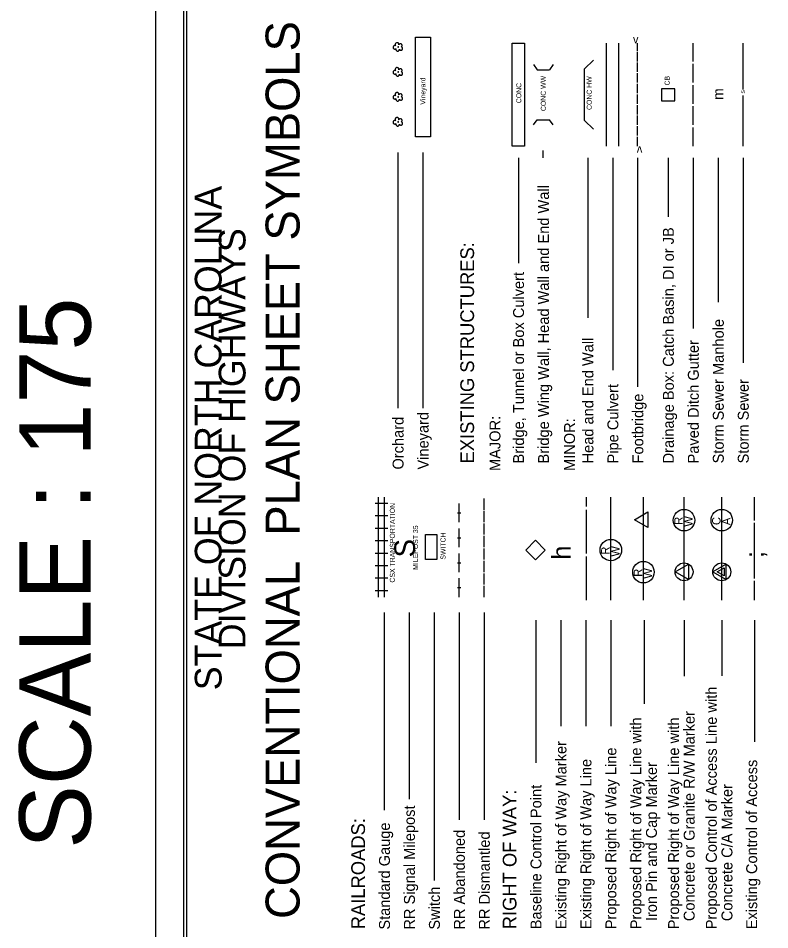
# Model space of a CAD drawing. Extents: x 2026893 to 2039781, y 729195 to 739590.
# Drawn here: x 2035191 to 2037298, y 735661 to 738217 of the extents above; entities that cross this region are included whole.
import ezdxf

# ---------------------------------------------------------------- set-up
doc = ezdxf.new("R2010")
doc.units = 0
for name, color, linetype in [('Scratch_Level_3', 7, 'Continuous'), ('Sheet Cutting Line CELL', 7, 'Continuous'), ('Sheet Plot Border Inside CELL', 7, 'Continuous'), ('Sheet Plot Border Outside CELL', 7, 'Continuous'), ('Sheet Symbology CELL', 7, 'Continuous')]:
    doc.layers.add(name, color=color, linetype=linetype)

msp = doc.modelspace()

# ---------------------------------------------------------------- linework, layer by layer
at = {"layer": 'Scratch_Level_3'}
msp.add_lwpolyline([(2036640.9, 736698.3), (2036613.5, 736725.7), (2036640.9, 736753.1), (2036668.3, 736725.7)], close=True, dxfattribs=at)
at = {"layer": 'Sheet Cutting Line CELL'}
msp.add_line((2035575.3, 739589.9), (2035575.3, 733695.9), dxfattribs=at)
at = {"layer": 'Sheet Plot Border Inside CELL'}
msp.add_lwpolyline([(2039346.7, 733741.4), (2039346.7, 739574.2), (2035653.9, 739574.2), (2035653.9, 733741.4)], close=True, dxfattribs=at)
at = {"layer": 'Sheet Plot Border Outside CELL'}
msp.add_lwpolyline([(2039425.3, 733695.9), (2039425.3, 739589.9), (2035575.3, 739589.9), (2035575.3, 733695.9)], close=True, dxfattribs=at)
at = {"layer": 'Sheet Symbology CELL'}
for p, q in [((2036839.7, 737858.5), (2036839.7, 738147.3)), ((2036874.7, 737858.5), (2036874.7, 738147.3)), ((2036927.2, 738126.3), (2036927.2, 738147.3)), ((2037082.7, 738096.5), (2037082.7, 738147.3)), ((2037222.7, 738017.9), (2037222.7, 738147.3)), ((2036927.2, 738096.5), (2036927.2, 738122.8)), ((2036635.2, 738087.3), (2036645.2, 738072.9)), ((2036690.2, 738087.3), (2036680.2, 738072.9)), ((2036778.5, 738075.1), (2036803.2, 738099.9)), ((2036927.2, 738066.8), (2036927.2, 738093)), ((2037082.7, 738037), (2037082.7, 738089.5)), ((2036645.2, 738072.9), (2036680.2, 738072.9)), ((2036778.5, 737930.7), (2036778.5, 738075.1)), ((2036927.2, 738037), (2036927.2, 738063.3)), ((2036927.2, 738007.3), (2036927.2, 738033.5)), ((2037082.7, 737977.5), (2037082.7, 738030)), ((2036927.2, 737977.5), (2036927.2, 738003.8)), ((2037222.7, 737858.5), (2037222.7, 738000.4)), ((2036927.2, 737947.8), (2036927.2, 737974)), ((2037082.7, 737918), (2037082.7, 737970.5)), ((2036635.2, 737918.6), (2036645.2, 737932.9)), ((2036645.2, 737932.9), (2036680.2, 737932.9)), ((2036690.2, 737918.6), (2036680.2, 737932.9)), ((2036803.2, 737906), (2036778.5, 737930.7)), ((2036927.2, 737918), (2036927.2, 737944.3)), ((2036927.2, 737888.3), (2036927.2, 737914.5)), ((2037082.7, 737858.5), (2037082.7, 737911)), ((2036927.2, 737858.5), (2036927.2, 737884.8)), ((2036255.1, 737841.1), (2036255.1, 737123.8)), ((2036325.1, 737841.1), (2036325.1, 737123.8)), ((2036592.7, 737826), (2036592.7, 737530.5)), ((2036662.7, 737826), (2036662.7, 737846.9)), ((2036787.2, 737826), (2036787.2, 737376.9)), ((2036857.2, 737826), (2036857.2, 737230.3)), ((2036927.2, 737826), (2036927.2, 737183.8)), ((2037012.7, 737826), (2037012.7, 737660.8)), ((2037082.7, 737826), (2037082.7, 737346.7)), ((2037152.7, 737826), (2037152.7, 737421.1)), ((2037222.7, 737826), (2037222.7, 737251.3)), ((2036226.4, 736856.4), (2036191.4, 736856.4)), ((2036200.2, 736838.9), (2036200.2, 736873.9)), ((2036217.7, 736838.9), (2036217.7, 736873.9)), ((2036426.8, 736803.9), (2036426.8, 736856.4)), ((2036496.8, 736838.9), (2036496.8, 736870.4)), ((2036783.6, 736847.7), (2036783.6, 736873.9)), ((2036852, 736585.2), (2036852, 736873.9)), ((2036943.4, 736585.2), (2036943.4, 736873.9)), ((2037057.2, 736585.2), (2037057.2, 736873.9)), ((2037163, 736585.2), (2037163, 736873.9)), ((2037254.3, 736808.7), (2037254.3, 736873.9)), ((2036200.2, 736803.9), (2036200.2, 736838.9)), ((2036217.7, 736803.9), (2036217.7, 736838.9)), ((2036422.5, 736830.2), (2036431.2, 736830.2)), ((2036496.8, 736803.9), (2036496.8, 736835.4)), ((2036783.6, 736716.4), (2036783.6, 736838.9)), ((2036226.4, 736821.4), (2036191.4, 736821.4)), ((2036200.2, 736768.9), (2036200.2, 736803.9)), ((2036217.7, 736768.9), (2036217.7, 736803.9)), ((2036943.4, 736810.8), (2036943.4, 736810.8)), ((2037254.3, 736646.3), (2037254.3, 736801.7)), ((2036226.4, 736786.4), (2036191.4, 736786.4)), ((2036426.8, 736733.9), (2036426.8, 736786.4)), ((2036496.8, 736768.9), (2036496.8, 736800.4)), ((2036226.4, 736751.4), (2036191.4, 736751.4)), ((2036200.2, 736733.9), (2036200.2, 736768.9)), ((2036217.7, 736733.9), (2036217.7, 736768.9)), ((2036422.5, 736760.2), (2036431.2, 736760.2)), ((2036496.8, 736733.9), (2036496.8, 736765.4)), ((2036200.2, 736698.9), (2036200.2, 736733.9)), ((2036217.7, 736698.9), (2036217.7, 736733.9)), ((2036496.8, 736698.9), (2036496.8, 736730.4)), ((2036226.4, 736716.4), (2036191.4, 736716.4)), ((2036426.8, 736663.9), (2036426.8, 736716.4)), ((2036783.6, 736585.2), (2036783.6, 736707.7)), ((2036226.4, 736681.4), (2036191.4, 736681.4)), ((2036200.2, 736663.9), (2036200.2, 736698.9)), ((2036217.7, 736663.9), (2036217.7, 736698.9)), ((2036422.5, 736690.2), (2036431.2, 736690.2)), ((2036496.8, 736663.9), (2036496.8, 736695.4)), ((2036200.2, 736628.9), (2036200.2, 736663.9)), ((2036217.7, 736628.9), (2036217.7, 736663.9)), ((2036496.8, 736628.9), (2036496.8, 736660.4)), ((2037057.2, 736664.6), (2037057.2, 736664.6)), ((2037163, 736664.6), (2037163, 736664.6)), ((2036226.4, 736646.4), (2036191.4, 736646.4)), ((2036200.2, 736593.9), (2036200.2, 736628.9)), ((2036217.7, 736593.9), (2036217.7, 736628.9)), ((2036426.8, 736593.9), (2036426.8, 736646.4)), ((2036496.8, 736593.9), (2036496.8, 736625.4)), ((2037254.3, 736585.2), (2037254.3, 736639.3)), ((2036226.4, 736611.4), (2036191.4, 736611.4)), ((2036422.5, 736620.2), (2036431.2, 736620.2)), ((2036216.8, 736550.6), (2036216.8, 735996.1)), ((2036286.8, 736550.6), (2036286.8, 736027.1)), ((2036356.8, 736550.6), (2036356.8, 735798.4)), ((2036426.8, 736550.6), (2036426.8, 735969)), ((2036496.8, 736550.6), (2036496.8, 735969)), ((2036496.8, 736550.6), (2036496.8, 735969)), ((2036641.6, 736529.1), (2036641.6, 736129.3)), ((2036711.6, 736529.1), (2036711.6, 736231.8)), ((2036781.6, 736529.1), (2036781.6, 736231.8)), ((2036851.6, 736529.1), (2036851.6, 736231.8)), ((2036945.5, 736529.1), (2036945.5, 736294.2)), ((2037057.7, 736529.1), (2037057.7, 736371.6)), ((2037163.5, 736529.1), (2037163.5, 736372.9)), ((2037254.3, 736529.1), (2037254.3, 736187.7))]:
    msp.add_line(p, q, dxfattribs=at)
for points in [[(2035662.8, 739530.4), (2035662.8, 734280.4), (2039334.3, 734280.4), (2039334.3, 739530.4)], [(2037031.3, 737986.1), (2037031.3, 738019.7), (2036994.1, 738019.7), (2036994.1, 737986.1)], [(2036956, 736788.9), (2036918.2, 736810.8), (2036956, 736832.6)], [(2036332.5, 736698.9), (2036332.5, 736768.9), (2036364.3, 736768.9), (2036364.3, 736698.9)], [(2037069.8, 736642.8), (2037032, 736664.6), (2037069.8, 736686.5)], [(2037175.6, 736642.8), (2037175.6, 736686.5), (2037137.8, 736664.6)], [(2037169.6, 736653.2), (2037149.9, 736664.6), (2037169.6, 736676.1)]]:
    msp.add_lwpolyline(points, close=True, dxfattribs=at)
for points in [[(2036304.1, 737884.5), (2036304.1, 738164.5), (2036346.1, 738164.5), (2036346.1, 737884.5), (2036304.1, 737884.5)], [(2036249, 738140.1), (2036247.9, 738140.7), (2036246.9, 738140.8), (2036245.8, 738140.7), (2036244.8, 738140.5), (2036243.9, 738140), (2036243, 738139.4), (2036242.3, 738138.6), (2036241.8, 738137.7), (2036241.4, 738136.5), (2036241.4, 738135.6), (2036241.6, 738134.5), (2036242, 738133.5), (2036242.5, 738132.6), (2036243.2, 738131.7), (2036244.2, 738131.2), (2036245.1, 738130.9), (2036246.2, 738130.7), (2036247.2, 738130.7), (2036248.3, 738130.9), (2036249.1, 738131.4), (2036250.2, 738132.1), (2036249.7, 738131.2), (2036249.5, 738130.2), (2036249.5, 738129.1), (2036249.8, 738128.2), (2036250.2, 738127.4), (2036250.9, 738126.5), (2036251.6, 738125.8), (2036252.5, 738125.3), (2036253.3, 738125.1), (2036254.6, 738124.9), (2036255.4, 738125.1), (2036256.3, 738125.4), (2036257.2, 738126.1), (2036257.9, 738126.7), (2036258.4, 738127.5), (2036258.9, 738128.6), (2036259.1, 738129.5), (2036259.1, 738130.5), (2036259.5, 738129.6), (2036260.2, 738128.8), (2036260.9, 738128.2), (2036261.9, 738127.9), (2036263, 738127.5), (2036263.8, 738127.5), (2036264.9, 738127.7), (2036265.8, 738128.2), (2036266.6, 738128.8), (2036267.3, 738129.5), (2036267.9, 738130.3), (2036268.2, 738131.2), (2036268.2, 738132.3), (2036268.2, 738133.3), (2036268, 738134.2), (2036267.3, 738135.1), (2036266.8, 738135.9), (2036265.2, 738136.8)], [(2036265.2, 738136.8), (2036266.5, 738138.9), (2036266.8, 738140), (2036267, 738141), (2036266.8, 738142.1), (2036266.5, 738142.9), (2036265.9, 738143.8), (2036265.2, 738144.7), (2036264.4, 738145.2), (2036263.5, 738145.6), (2036262.4, 738145.9), (2036261.4, 738145.7), (2036260.3, 738145.6), (2036259.3, 738144.9), (2036258.6, 738144.3), (2036258.1, 738143.5), (2036257.5, 738142.4), (2036257.7, 738143.5), (2036257.7, 738144.7), (2036257.4, 738145.6), (2036256.8, 738146.6), (2036256.3, 738147.5), (2036255.4, 738148.2), (2036254.4, 738148.7), (2036253.3, 738148.9), (2036252.3, 738149.1), (2036251.2, 738148.9), (2036250.2, 738148.5), (2036249.3, 738147.8), (2036248.4, 738147), (2036247.9, 738146.1), (2036247.6, 738145), (2036247.4, 738144), (2036247.4, 738142.9), (2036247.7, 738141.9), (2036248.3, 738141), (2036249, 738140.1)], [(2036255.1, 738137.2), (2036255.1, 738136.6), (2036255.3, 738136.3), (2036255.4, 738135.9), (2036256, 738135.9), (2036256.3, 738135.9), (2036256.7, 738136.3), (2036256.7, 738136.8), (2036256.7, 738137.2), (2036256.3, 738137.5), (2036255.8, 738137.7), (2036255.4, 738137.5), (2036255.1, 738137.2)], [(2036575.2, 737858.5), (2036575.2, 738147.3), (2036610.2, 738147.3), (2036610.2, 737858.5), (2036575.2, 737858.5)], [(2036249, 738070.1), (2036247.9, 738070.7), (2036246.9, 738070.8), (2036245.8, 738070.7), (2036244.8, 738070.5), (2036243.9, 738070), (2036243, 738069.4), (2036242.3, 738068.6), (2036241.8, 738067.7), (2036241.4, 738066.5), (2036241.4, 738065.6), (2036241.6, 738064.5), (2036242, 738063.5), (2036242.5, 738062.6), (2036243.2, 738061.7), (2036244.2, 738061.2), (2036245.1, 738060.9), (2036246.2, 738060.7), (2036247.2, 738060.7), (2036248.3, 738060.9), (2036249.1, 738061.4), (2036250.2, 738062.1), (2036249.7, 738061.2), (2036249.5, 738060.2), (2036249.5, 738059.1), (2036249.8, 738058.2), (2036250.2, 738057.4), (2036250.9, 738056.5), (2036251.6, 738055.8), (2036252.5, 738055.3), (2036253.3, 738055.1), (2036254.6, 738054.9), (2036255.4, 738055.1), (2036256.3, 738055.4), (2036257.2, 738056.1), (2036257.9, 738056.7), (2036258.4, 738057.5), (2036258.9, 738058.6), (2036259.1, 738059.5), (2036259.1, 738060.5), (2036259.5, 738059.6), (2036260.2, 738058.8), (2036260.9, 738058.2), (2036261.9, 738057.9), (2036263, 738057.5), (2036263.8, 738057.5), (2036264.9, 738057.7), (2036265.8, 738058.2), (2036266.6, 738058.8), (2036267.3, 738059.5), (2036267.9, 738060.3), (2036268.2, 738061.2), (2036268.2, 738062.3), (2036268.2, 738063.3), (2036268, 738064.2), (2036267.3, 738065.1), (2036266.8, 738065.9), (2036265.2, 738066.8)], [(2036265.2, 738066.8), (2036266.5, 738068.9), (2036266.8, 738070), (2036267, 738071), (2036266.8, 738072.1), (2036266.5, 738072.9), (2036265.9, 738073.8), (2036265.2, 738074.7), (2036264.4, 738075.2), (2036263.5, 738075.6), (2036262.4, 738075.9), (2036261.4, 738075.7), (2036260.3, 738075.6), (2036259.3, 738074.9), (2036258.6, 738074.3), (2036258.1, 738073.5), (2036257.5, 738072.4), (2036257.7, 738073.5), (2036257.7, 738074.7), (2036257.4, 738075.6), (2036256.8, 738076.6), (2036256.3, 738077.5), (2036255.4, 738078.2), (2036254.4, 738078.7), (2036253.3, 738078.9), (2036252.3, 738079.1), (2036251.2, 738078.9), (2036250.2, 738078.5), (2036249.3, 738077.8), (2036248.4, 738077), (2036247.9, 738076.1), (2036247.6, 738075), (2036247.4, 738074), (2036247.4, 738072.9), (2036247.7, 738071.9), (2036248.3, 738071), (2036249, 738070.1)], [(2036255.1, 738067.2), (2036255.1, 738066.6), (2036255.3, 738066.3), (2036255.4, 738065.9), (2036256, 738065.9), (2036256.3, 738065.9), (2036256.7, 738066.3), (2036256.7, 738066.8), (2036256.7, 738067.2), (2036256.3, 738067.5), (2036255.8, 738067.7), (2036255.4, 738067.5), (2036255.1, 738067.2)], [(2036265.2, 737996.8), (2036266.5, 737998.9), (2036266.8, 738000), (2036267, 738001), (2036266.8, 738002.1), (2036266.5, 738002.9), (2036265.9, 738003.8), (2036265.2, 738004.7), (2036264.4, 738005.2), (2036263.5, 738005.6), (2036262.4, 738005.9), (2036261.4, 738005.7), (2036260.3, 738005.6), (2036259.3, 738004.9), (2036258.6, 738004.3), (2036258.1, 738003.5), (2036257.5, 738002.4), (2036257.7, 738003.5), (2036257.7, 738004.7), (2036257.4, 738005.6), (2036256.8, 738006.6), (2036256.3, 738007.5), (2036255.4, 738008.2), (2036254.4, 738008.7), (2036253.3, 738008.9), (2036252.3, 738009.1), (2036251.2, 738008.9), (2036250.2, 738008.5), (2036249.3, 738007.8), (2036248.4, 738007), (2036247.9, 738006.1), (2036247.6, 738005), (2036247.4, 738004), (2036247.4, 738002.9), (2036247.7, 738001.9), (2036248.3, 738001), (2036249, 738000.1)], [(2036249, 738000.1), (2036247.9, 738000.7), (2036246.9, 738000.8), (2036245.8, 738000.7), (2036244.8, 738000.5), (2036243.9, 738000), (2036243, 737999.4), (2036242.3, 737998.6), (2036241.8, 737997.7), (2036241.4, 737996.5), (2036241.4, 737995.6), (2036241.6, 737994.5), (2036242, 737993.5), (2036242.5, 737992.6), (2036243.2, 737991.7), (2036244.2, 737991.2), (2036245.1, 737990.9), (2036246.2, 737990.7), (2036247.2, 737990.7), (2036248.3, 737990.9), (2036249.1, 737991.4), (2036250.2, 737992.1), (2036249.7, 737991.2), (2036249.5, 737990.2), (2036249.5, 737989.1), (2036249.8, 737988.2), (2036250.2, 737987.4), (2036250.9, 737986.5), (2036251.6, 737985.8), (2036252.5, 737985.3), (2036253.3, 737985.1), (2036254.6, 737984.9), (2036255.4, 737985.1), (2036256.3, 737985.4), (2036257.2, 737986.1), (2036257.9, 737986.7), (2036258.4, 737987.5), (2036258.9, 737988.6), (2036259.1, 737989.5), (2036259.1, 737990.5), (2036259.5, 737989.6), (2036260.2, 737988.8), (2036260.9, 737988.2), (2036261.9, 737987.9), (2036263, 737987.5), (2036263.8, 737987.5), (2036264.9, 737987.7), (2036265.8, 737988.2), (2036266.6, 737988.8), (2036267.3, 737989.5), (2036267.9, 737990.3), (2036268.2, 737991.2), (2036268.2, 737992.3), (2036268.2, 737993.3), (2036268, 737994.2), (2036267.3, 737995.1), (2036266.8, 737995.9), (2036265.2, 737996.8)], [(2036255.1, 737997.2), (2036255.1, 737996.6), (2036255.3, 737996.3), (2036255.4, 737995.9), (2036256, 737995.9), (2036256.3, 737995.9), (2036256.7, 737996.3), (2036256.7, 737996.8), (2036256.7, 737997.2), (2036256.3, 737997.5), (2036255.8, 737997.7), (2036255.4, 737997.5), (2036255.1, 737997.2)], [(2036249, 737930.1), (2036247.9, 737930.7), (2036246.9, 737930.8), (2036245.8, 737930.7), (2036244.8, 737930.5), (2036243.9, 737930), (2036243, 737929.4), (2036242.3, 737928.6), (2036241.8, 737927.7), (2036241.4, 737926.5), (2036241.4, 737925.6), (2036241.6, 737924.5), (2036242, 737923.5), (2036242.5, 737922.6), (2036243.2, 737921.7), (2036244.2, 737921.2), (2036245.1, 737920.9), (2036246.2, 737920.7), (2036247.2, 737920.7), (2036248.3, 737920.9), (2036249.1, 737921.4), (2036250.2, 737922.1), (2036249.7, 737921.2), (2036249.5, 737920.2), (2036249.5, 737919.1), (2036249.8, 737918.2), (2036250.2, 737917.4), (2036250.9, 737916.5), (2036251.6, 737915.8), (2036252.5, 737915.3), (2036253.3, 737915.1), (2036254.6, 737914.9), (2036255.4, 737915.1), (2036256.3, 737915.4), (2036257.2, 737916.1), (2036257.9, 737916.7), (2036258.4, 737917.5), (2036258.9, 737918.6), (2036259.1, 737919.5), (2036259.1, 737920.5), (2036259.5, 737919.6), (2036260.2, 737918.8), (2036260.9, 737918.2), (2036261.9, 737917.9), (2036263, 737917.5), (2036263.8, 737917.5), (2036264.9, 737917.7), (2036265.8, 737918.2), (2036266.6, 737918.8), (2036267.3, 737919.5), (2036267.9, 737920.3), (2036268.2, 737921.2), (2036268.2, 737922.3), (2036268.2, 737923.3), (2036268, 737924.2), (2036267.3, 737925.1), (2036266.8, 737925.9), (2036265.2, 737926.8)], [(2036265.2, 737926.8), (2036266.5, 737928.9), (2036266.8, 737930), (2036267, 737931), (2036266.8, 737932.1), (2036266.5, 737932.9), (2036265.9, 737933.8), (2036265.2, 737934.7), (2036264.4, 737935.2), (2036263.5, 737935.6), (2036262.4, 737935.9), (2036261.4, 737935.7), (2036260.3, 737935.6), (2036259.3, 737934.9), (2036258.6, 737934.3), (2036258.1, 737933.5), (2036257.5, 737932.4), (2036257.7, 737933.5), (2036257.7, 737934.7), (2036257.4, 737935.6), (2036256.8, 737936.6), (2036256.3, 737937.5), (2036255.4, 737938.2), (2036254.4, 737938.7), (2036253.3, 737938.9), (2036252.3, 737939.1), (2036251.2, 737938.9), (2036250.2, 737938.5), (2036249.3, 737937.8), (2036248.4, 737937), (2036247.9, 737936.1), (2036247.6, 737935), (2036247.4, 737934), (2036247.4, 737932.9), (2036247.7, 737931.9), (2036248.3, 737931), (2036249, 737930.1)], [(2036255.1, 737927.2), (2036255.1, 737926.6), (2036255.3, 737926.3), (2036255.4, 737925.9), (2036256, 737925.9), (2036256.3, 737925.9), (2036256.7, 737926.3), (2036256.7, 737926.8), (2036256.7, 737927.2), (2036256.3, 737927.5), (2036255.8, 737927.7), (2036255.4, 737927.5), (2036255.1, 737927.2)]]:
    msp.add_lwpolyline(points, dxfattribs=at)
for centre, radius in [((2037057.2, 736809.5), 30.1), ((2037163, 736809.5), 30.1), ((2036852, 736725.6), 30.1), ((2036943.4, 736663.7), 30.1), ((2037057.2, 736664.6), 25.2), ((2037163, 736664.6), 25.2)]:
    msp.add_circle(centre, radius, dxfattribs=at)

# ---------------------------------------------------------------- texts
at = {"layer": 'Scratch_Level_3'}
msp.add_text(' SCALE : 175', height=200, rotation=90, dxfattribs=at).set_placement((2035393.7, 735813.6))
at = {"layer": 'Sheet Symbology CELL'}
for s, height, rotation, p in [('CONVENTIONAL  PLAN SHEET SYMBOLS', 95.201, 90, (2035979.4, 735690.9)), ('v', 23.1, 0.2409, (2036914.1, 738147.2)), ('Vineyard', 14, 90, (2036332.1, 737974.9)), ('CONC', 14, 90, (2036601, 737979.1)), ('CONC WW', 14, 90, (2036669.7, 737957)), ('CONC HW', 14, 90, (2036798.3, 737960.2)), ('CB', 14, 90, (2037016.8, 738028.9)), ('m', 28.9, 90, (2037167.1, 737988.5)), ('S', 10.5, 90, (2037228, 738006)), ('v', 23.1, 179.7591, (2036940.3, 737858.5)), ('STATE OF NORTH CAROLINA', 74.966, 90, (2035760.7, 736332.5)), ('Bridge Wing Wall, Head Wall and End Wall', 30.625, 90, (2036678.6, 736968.6)), ('DIVISION OF HIGHWAYS', 74.966, 90, (2035827.8, 736447.5)), ('Drainage Box: Catch Basin, DI or JB', 30.625, 90, (2037028.6, 736968.7)), ('EXISTING STRUCTURES:', 38.5, 90, (2036468.6, 736968.6)), ('Bridge, Tunnel or Box Culvert', 30.625, 90, (2036608.6, 736968.6)), ('Storm Sewer Manhole', 30.625, 90, (2037168.6, 736968.7)), ('Head and End Wall', 30.625, 90, (2036803.1, 736968.6)), ('Paved Ditch Gutter', 30.625, 90, (2037098.6, 736968.7)), ('Pipe Culvert', 30.625, 90, (2036873.1, 736968.6)), ('Storm Sewer', 30.625, 90, (2037238.6, 736968.7)), ('Footbridge', 30.63, 90, (2036943.1, 736968.7)), ('Vineyard', 30.63, 90, (2036340.9, 736951.5)), ('Orchard', 30.63, 90, (2036270.9, 736951.5)), ('MAJOR:', 30.63, 90, (2036542.5, 736947.5)), ('MINOR:', 30.63, 90, (2036751.5, 736947.5)), ('CSX TRANSPORTATION', 14, 90, (2036246.5, 736634.4)), ('R', 23.6, 90, (2037053.6, 736796.5)), ('W', 23.6, 90, (2037081.5, 736791.2)), ('C', 23.6, 90, (2037159.5, 736795.7)), ('A', 23.6, 90, (2037187.3, 736795.4)), ('MILEPOST 35', 14, 90, (2036311.5, 736670.1)), ('S', 57.8, 90, (2036303, 736705.1)), ('SWITCH', 14, 90, (2036388.5, 736698.8)), ('h', 52.5, 90, (2036739.8, 736699)), ('R', 23.6, 90, (2036848.4, 736712.6)), ('W', 23.6, 90, (2036876.3, 736707.2)), (';', 52.5, 90, (2037280.6, 736703.3)), ('W', 23.6, 90, (2036967.7, 736645.3)), ('R', 23.6, 90, (2036939.9, 736650.7)), ('Proposed Control of Access Line with', 30.625, 90, (2037149.1, 735662)), ('  Concrete or Granite R/W Marker', 30.625, 90, (2037087, 735662)), ('Proposed Right of Way Line with', 30.625, 90, (2036937.5, 735662)), ('Proposed Right of Way Line with', 30.625, 90, (2037043.3, 735662)), ('Existing Right of Way Marker', 30.625, 90, (2036727.5, 735662)), ('Proposed Right of Way Line', 30.625, 90, (2036867.5, 735662)), ('Existing Right of Way Line', 30.625, 90, (2036797.5, 735662)), ('  Iron Pin and Cap Marker', 30.625, 90, (2036981.2, 735662)), ('Existing Control of Access', 30.625, 90, (2037262.2, 735662)), ('Baseline Control Point', 30.625, 90, (2036657.5, 735662)), ('  Concrete C/A Marker', 30.625, 90, (2037192.9, 735662)), ('RIGHT OF WAY:', 38.5, 90, (2036587.5, 735662)), ('RR Signal Milepost', 30.625, 90, (2036302.7, 735661)), ('RAILROADS:', 38.5, 90, (2036162.8, 735662)), ('Standard Gauge', 30.625, 90, (2036232.7, 735661)), ('RR Abandoned', 30.625, 90, (2036442.7, 735661)), ('RR Dismantled', 30.625, 90, (2036512.7, 735661)), ('Switch', 30.63, 90, (2036372.7, 735661))]:
    msp.add_text(s, height=height, rotation=rotation, dxfattribs=at).set_placement(p)

doc.saveas('drawing.dxf')
